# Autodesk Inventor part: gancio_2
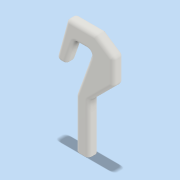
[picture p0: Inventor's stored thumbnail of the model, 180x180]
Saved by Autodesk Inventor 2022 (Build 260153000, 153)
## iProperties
Created: 2022-10
Part Number: gancio_2
Material: Acciaio, Alta resistenza, Bassa lega
Document SubType Name: Modeling
Designer: x300
Density: 7.85 g/cm^3
Appearance: Acciaio
Mass: 4773.61 g
Surface Area: 656.04 cm^2
Volume: 608.103 cm^3
Author: x300
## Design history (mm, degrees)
sketch "Schizzo1"
  geometry: L1 (-12.897, -170.425)-(23.98, -170.425); L2 (23.98, -170.425)-(23.98, -27.327); L3 (23.98, -27.327)-(-12.897, -27.327); L4 (-12.897, -27.327)-(-12.897, -170.425); L5 (-12.897, -27.327)-(33.465, 102.142); L6 (33.465, 102.142)-(-18.374, 102.142); L7 (-18.374, 102.142)-(-42.824, 31.194); L8 (-42.824, 31.194)-(-71.419, 31.194); L9 (-71.419, 31.194)-(-39.24, 148.973); L10 (95.525, 44.003)-(23.98, -27.327); L11 (95.525, 44.003)-(95.525, 114.545); L12 (95.525, 114.545)-(43.797, 148.973); L13 (43.797, 148.973)-(-39.24, 148.973); 1 further point
  constraints: 26 end point, 3 parallel, 2 horizontal, 2 perpendicular, 1 vertical
extrude "Estrusione1" new body sketch "Schizzo1" stored distance "d0" = 30; taper "d1" = 0 deg
fillet "Raccordo1" dims "d2" = 10
fillet "Raccordo2" dims "d3" = 10
fillet "Raccordo3" dims "d4" = 10
node "Solido1"
other parameters: "sa_0" = 9810000
